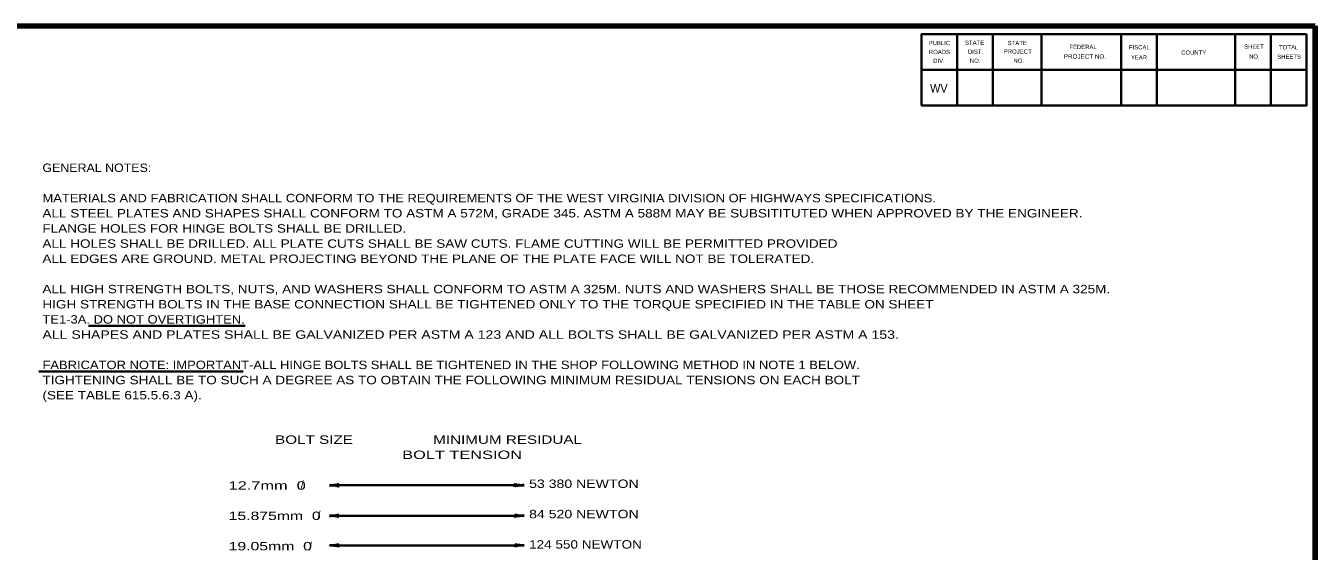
# Model space of a CAD drawing. Extents: x -27 to 686, y -9 to 444.
# Drawn here: x 298 to 680.6, y 283.1 to 439 of the extents above; entities that cross this region are included whole.
import ezdxf
from ezdxf.enums import TextEntityAlignment as Align

# ---------------------------------------------------------------- set-up
doc = ezdxf.new("R2010")
doc.units = 0
doc.layers.add('1', color=7, linetype='Continuous', lineweight=53)
doc.layers.add('61', color=7, linetype='Continuous', lineweight=35)

msp = doc.modelspace()

# ---------------------------------------------------------------- linework, layer by layer
at = {"layer": '1', "lineweight": 158}
msp.add_line((680.552, 0.589), (680.552, 439.006), dxfattribs=at)
at = {"layer": '1', "lineweight": 13}
msp.add_line((680.552, 0.589), (680.552, 439.006), dxfattribs=at)
at = {"layer": '1', "lineweight": 35}
for p, q in [((316.635, 349.935), (363.063, 349.935)), ((301.921, 336.353), (362.565, 336.353)), ((388.09, 302.633), (445.846, 302.633)), ((388.09, 293.59), (445.846, 293.59)), ((388.09, 284.802), (445.846, 284.802))]:
    msp.add_line(p, q, dxfattribs=at)
at = {"layer": '1', "lineweight": 158}
msp.add_lwpolyline([(680.552, 439.006), (20.802, 438.923), (20.886, 0.589)], dxfattribs=at)
at = {"layer": '1', "lineweight": 40}
for centre, major_axis, ratio, start_param, end_param in [((389.181, 302.909), (-1.786, -0.156), 0.122415, 0.8963533, 3.1415927), ((389.211, 302.421), (-1.756, 0.176), 0.07063, 3.1407148, 5.41811), ((444.755, 302.357), (1.786, 0.156), 0.122415, 0.8963533, 3.1415927), ((444.755, 302.357), (1.786, 0.156), 0.122415, 0.8963533, 3.1415927), ((444.725, 302.844), (1.756, -0.176), 0.07063, 3.1407148, 5.41811), ((444.725, 302.844), (1.756, -0.176), 0.07063, 3.1407148, 5.41811), ((389.181, 293.867), (-1.786, -0.156), 0.122415, 0.8963533, 3.1415927), ((389.211, 293.379), (-1.756, 0.176), 0.07063, 3.1407148, 5.41811), ((444.755, 293.314), (1.786, 0.156), 0.122415, 0.8963533, 3.1415927), ((444.755, 293.314), (1.786, 0.156), 0.122415, 0.8963533, 3.1415927), ((444.725, 293.802), (1.756, -0.176), 0.07063, 3.1407148, 5.41811), ((444.725, 293.802), (1.756, -0.176), 0.07063, 3.1407148, 5.41811), ((389.181, 285.078), (-1.786, -0.156), 0.122415, 0.8963533, 3.1415927), ((389.181, 285.078), (-1.786, -0.156), 0.122415, 0.8963533, 3.1415927), ((389.211, 284.59), (-1.756, 0.176), 0.07063, 3.1407148, 5.41811), ((389.211, 284.59), (-1.756, 0.176), 0.07063, 3.1407148, 5.41811), ((444.755, 284.525), (1.786, 0.156), 0.122415, 0.8963533, 3.1415927), ((444.755, 284.525), (1.786, 0.156), 0.122415, 0.8963533, 3.1415927), ((444.725, 285.013), (1.756, -0.176), 0.07063, 3.1407148, 5.41811), ((444.725, 285.013), (1.756, -0.176), 0.07063, 3.1407148, 5.41811)]:
    msp.add_ellipse(centre, major_axis=major_axis, ratio=ratio, start_param=start_param, end_param=end_param, dxfattribs=at)
at = {"layer": '61'}
for p, q in [((574.302, 436.506), (574.302, 415.339)), ((584.886, 436.506), (584.886, 415.339)), ((599.386, 436.506), (599.386, 415.339)), ((622.969, 436.506), (622.969, 415.339)), ((633.552, 436.506), (633.552, 415.339)), ((656.802, 436.506), (656.802, 415.339)), ((667.386, 436.506), (667.386, 415.339)), ((677.969, 425.923), (563.719, 425.923))]:
    msp.add_line(p, q, dxfattribs=at)
for points in [[(677.969, 436.506), (563.719, 436.506), (563.719, 415.339)], [(677.969, 436.506), (677.969, 415.339), (563.719, 415.339)]]:
    msp.add_lwpolyline(points, dxfattribs=at)

# ---------------------------------------------------------------- texts
at = {"layer": '1'}
for s, height, width, p in [('WV', 2.54, 0.95, (566.302, 419.173)), ('GENERAL NOTES:', 2.5, 1.1, (302.967, 395.611)), ('MATERIALS AND FABRICATION SHALL CONFORM TO THE REQUIREMENTS OF THE WEST VIRGINIA DIVISION OF HIGHWAYS SPECIFICATIONS.', 2.5, 1.15, (302.967, 386.611)), ('ALL STEEL PLATES AND SHAPES SHALL CONFORM TO ASTM A 572M, GRADE 345. ASTM A 588M MAY BE SUBSITITUTED WHEN APPROVED BY THE ENGINEER.', 2.5, 1.2, (302.967, 382.111)), ('FLANGE HOLES FOR HINGE BOLTS SHALL BE DRILLED.', 2.5, 1.2, (302.967, 377.611)), ('ALL HOLES SHALL BE DRILLED. ALL PLATE CUTS SHALL BE SAW CUTS. FLAME CUTTING WILL BE PERMITTED PROVIDED', 2.5, 1.2, (302.967, 373.111)), ('ALL EDGES ARE GROUND. METAL PROJECTING BEYOND THE PLANE OF THE PLATE FACE WILL NOT BE TOLERATED.', 2.5, 1.2, (302.967, 368.611)), ('ALL HIGH STRENGTH BOLTS, NUTS, AND WASHERS SHALL CONFORM TO ASTM A 325M. NUTS AND WASHERS SHALL BE THOSE RECOMMENDED IN ASTM A 325M.', 2.5, 1.2, (302.967, 359.611)), ('HIGH STRENGTH BOLTS IN THE BASE CONNECTION SHALL BE TIGHTENED ONLY TO THE TORQUE SPECIFIED IN THE TABLE ON SHEET', 2.5, 1.2, (302.967, 355.111)), ('TE1-3A. DO NOT OVERTIGHTEN.', 2.5, 1.15, (302.967, 350.611)), ('ALL SHAPES AND PLATES SHALL BE GALVANIZED PER ASTM A 123 AND ALL BOLTS SHALL BE GALVANIZED PER ASTM A 153.', 2.5, 1.25, (302.967, 346.111)), ('FABRICATOR NOTE: IMPORTANT-ALL HINGE BOLTS SHALL BE TIGHTENED IN THE SHOP FOLLOWING METHOD IN NOTE 1 BELOW.', 2.5, 1.15, (302.967, 337.111)), ('TIGHTENING SHALL BE TO SUCH A DEGREE AS TO OBTAIN THE FOLLOWING MINIMUM RESIDUAL TENSIONS ON EACH BOLT', 2.5, 1.2, (302.967, 332.611)), ('(SEE TABLE 615.5.6.3 A).', 2.5, 1.2, (302.967, 328.111)), ('BOLT SIZE                   MINIMUM RESIDUAL', 2.5, 1.35, (371.994, 314.927)), ('                            BOLT TENSION', 2.5, 1.45, (371.994, 310.427)), ('12.7mm  0', 2.5, 1.45, (358.193, 301.312)), ('53 380 NEWTON', 2.5, 1.25, (447.343, 301.835)), ('15.875mm  0', 2.5, 1.4, (358.193, 292.312)), ('84 520 NEWTON', 2.5, 1.25, (447.343, 292.835)), ('19.05mm  0', 2.5, 1.4, (358.193, 283.312)), ('124 550 NEWTON', 2.5, 1.2, (447.343, 283.835))]:
    msp.add_text(s, height=height, dxfattribs=dict(at, width=width)).set_placement(p)
for p in [(380.021, 301.426), (384.988, 292.421), (382.461, 283.285)]:
    msp.add_text('/', height=2.5, dxfattribs=at).set_placement(p, align=Align.CENTER)
at = {"layer": '61'}
for s, height, rotation, p in [('PUBLIC', 1.271, 0.033, (565.886, 433.256)), ('FEDERAL', 1.27, 0.007, (607.636, 432.089)), ('FISCAL', 1.271, 359.942, (625.302, 432.006)), ('SHEET', 1.271, 0.059, (659.469, 432.173)), ('ROADS', 1.27, 0.124, (565.969, 430.589)), ('DIV.', 1.27, 359.932, (567.219, 428.006)), ('DIST.', 1.27, 0.056, (577.552, 430.673)), ('YEAR', 1.27, 0.105, (625.886, 429.006)), ('COUNTY', 1.269, 0.069, (640.802, 430.423)), ('SHEETS', 1.269, 359.959, (669.302, 429.173))]:
    msp.add_text(s, height=height, rotation=rotation, dxfattribs=at).set_placement(p)
for s, height, rotation, width, p in [('STATE', 1.271, 0.059, 1.05, (576.636, 433.339)), ('STATE', 1.271, 0.059, 1.05, (589.302, 433.256)), ('TOTAL', 1.27, 359.926, 1.05, (669.802, 432.006)), ('NO.', 1.27, 359.852, 0.9, (578.136, 428.006)), ('PROJECT', 1.27, 359.908, 1.05, (588.136, 430.756)), ('NO.', 1.271, 0.225, 0.9, (591.052, 428.006)), ('PROJECT NO.', 1.27, 359.922, 1.1, (605.969, 429.256)), ('NO.', 1.27, 359.852, 0.9, (660.969, 429.256))]:
    msp.add_text(s, height=height, rotation=rotation, dxfattribs=dict(at, width=width)).set_placement(p)

doc.saveas('drawing.dxf')
